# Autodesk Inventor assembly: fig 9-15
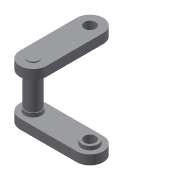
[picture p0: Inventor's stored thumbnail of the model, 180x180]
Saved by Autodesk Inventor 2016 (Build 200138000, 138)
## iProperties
Shininess: 64.0
Length Units: 11269
Angle Units: 11279
Time Units: 11290
Mass Units: 11283
Length Display Precision: 3
Angle Display Precision: 2
Created: 2002-01
Part Number: fig 9-15
Document SubType Name: Assembly
Designer: ***
Density: 0.0
Volumn: 0.0
Area: 0.0
PropertySet Name: Model Information
Control State: 0
Master: False
Checked Out: False
Author: ***
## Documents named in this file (3)
- D:\KAVITA\Autodesk Inventor_ 2016 Project_Kavita\Inventor_Part Files\Inventor_2016_Part\c09_Inv_2016\c09_inv_2016_prt\fig 9-15.iam
- D:\KAVITA\Autodesk Inventor_ 2016 Project_Kavita\Inventor_Part Files\Inventor_2016_Part\c09_Inv_2016\c09_inv_2016_prt\Part5.ipt
- D:\KAVITA\Autodesk Inventor_ 2016 Project_Kavita\Inventor_Part Files\Inventor_2016_Part\c09_Inv_2016\c09_inv_2016_prt\Part6.ipt
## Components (3 placed, 2 different names)
1. Part5:1 — Insert:1, Angle:1
2. Part6:1 — Insert:1, Insert:2
3. Part5:2 — Insert:2, Angle:1
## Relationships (3: Insert 2, Angle 1)
- Insert:1: Part5:1 ↔ Part6:1
- Insert:2: Part6:1 ↔ Part5:2
- Angle:1: Part5:1 ↔ Part5:2
